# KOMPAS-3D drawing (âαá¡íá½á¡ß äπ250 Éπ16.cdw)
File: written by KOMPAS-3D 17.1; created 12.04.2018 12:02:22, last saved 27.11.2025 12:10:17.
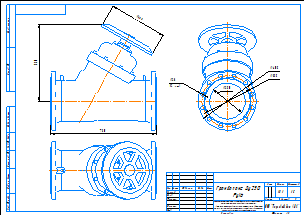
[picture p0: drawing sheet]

Sheet 1: A3, landscape

Title block, sheet 1: name: Гранбаланс Ду250 / Ру16; material: Сталь 20  ГОСТ 1050-88; mass: 181; sheets: 1; sheet format: A3; stored path: C:\Users\kka\KOMPAS_Work\!Trash\КМ125 КМ127 КМ225Ф Двухходовые клапана\КМ125Ф + PSL\KOMPAS 2D\Гранрег КМ125Ф Ду32 Ру16.cdw

Views: Спереди 1, Спереди
Referenced files in C:\Users\mipv\Desktop\КБЧ\Имеющиеся\: Гранбаланс Ду250 Ру16  серия 10.m3d
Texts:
  kka
  adl
  Рама для чертежей
  Лит-Масса-Масштаб
  Материал-Предприятие
  Масштаб
  Изм.
  Лист
  № докум.
  Подп.
  Дата
  Лит.
  Разраб.
  Пров.
  Т.контр.
  Листов
  Внимание! Данный продукт является объектом авторского права ООО «Торговый Дом АДЛ».
  Запрещается изменение, копирование, распространение
  (в том числе путем копирования на другие сайты и ресурсы в Интернете)
  или любое иное использование информации и объектов без предварительного
  согласия правообладателя (ООО «Торговый Дом АДЛ»).
  Н.контр.
  Утв.
  ООО "Торговый дом АДЛ"
  Изменение
  Номер документа
  Подпись
  Обозначение документа
  Наименование изделия
  Масса изделия по ГОСТ 2.109-73
  Порядковый номер листа
  Общее количество листов в документе
  Характер работы, выполненной лицом, подписавшим документ
  Наименование или индекс предприятия, выпускающего документ
  Инв. № подл.
  Подп. и дата
  Взам. инв. №
  Инв. № дубл.
  Инвентарный номер подлинника по ГОСТ 2.501-68
  Подпись принявшего подлинник в отдел технической документации
  Инвентарный номер подлинника, взамен которого выпущен данный подлинник
  Инвентарный номер дубликата по ГОСТ 2.502-68
  Подпись принявшего дубликат в отдел технической документации
  Справ. №
  Перв. примен.
  Обозначение документа, взамен или на основании которого выпущен данный документ
  Обозначение документа, в котором впервые записан данный документ
  Подпись лица, копировавшего чертеж
  Обозначение формата листа
  !Рама для чертежа
Dimensions and other numbers on the sheet: 730; 530; 400; 1:5; 1; 181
